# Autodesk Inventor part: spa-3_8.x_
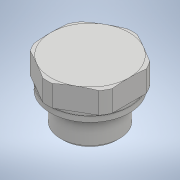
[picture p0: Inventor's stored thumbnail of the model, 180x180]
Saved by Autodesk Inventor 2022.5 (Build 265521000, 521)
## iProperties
Created: 2018-04
Part Number: spa-3_8.x_
Material: 一般
Document SubType Name: Modeling
Designer: imaocorp
Density: 1 g/cm^3
Appearance: 既定
Sending System: SOLIDWORKS 2016-2016286
MC: AMD64
MC_MODEL: AMD64 Family 21 Model 2 Stepping 0, AuthenticAMD
OS: Windows_NT
FRU: Parasolid Version 28.0, build 224,  7-29-2016
FORMAT: text
GUISE: transmit
KEY: spa-3_8
FILE: spa-3_8.x_t
DATE: Wed Apr 25 10:16:17 2018
Author: imaocorp
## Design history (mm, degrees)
feature "Base1"
node "ソリッド1"
